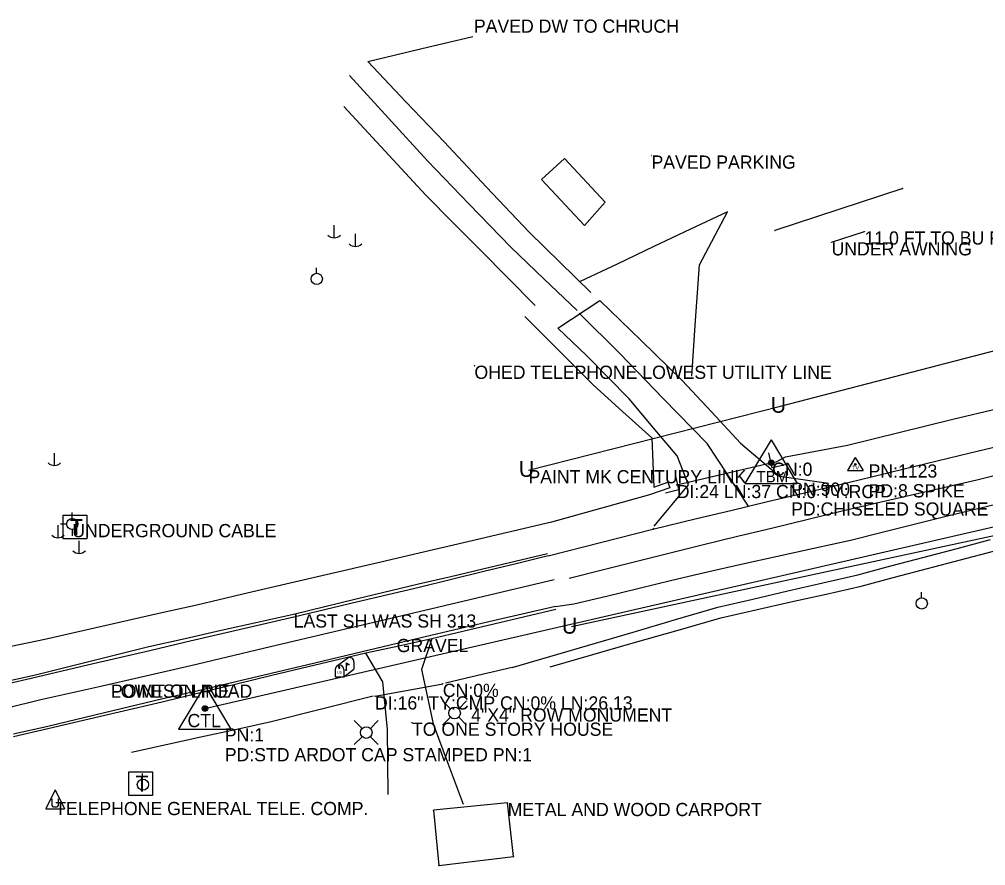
# Model space of a CAD drawing. Extents: x 1568433 to 1572450, y 731863 to 733450.
# Drawn here: x 1569044.4 to 1569410.1, y 731914 to 732234.5 of the extents above; entities that cross this region are included whole.
import ezdxf

# ---------------------------------------------------------------- set-up
doc = ezdxf.new("R2010")
doc.units = 0
for name, color, linetype in [('Default', 7, 'Continuous'), ('S_BASELINE', 7, 'Continuous'), ('S_BUILDING', 7, 'Continuous'), ('S_BUILDING_ANNOT', 7, 'Continuous'), ('S_CROSS_DRAIN', 7, 'Continuous'), ('S_CROSS_DRAIN_ANNOT', 7, 'Continuous'), ('S_DITCHLINE', 7, 'Continuous'), ('S_DRG_PT_SYM', 7, 'Continuous'), ('S_DRIVEWAY', 7, 'Continuous'), ('S_DRIVEWAY_ANNOT', 7, 'Continuous'), ('S_EDGE_BITUMINOUS', 7, 'Continuous'), ('S_EDGE_PAVEMENT', 7, 'Continuous'), ('S_EDGE_PAVEMENT_ANNOT', 7, 'Continuous'), ('S_ELECTRIC_UTILITIES_ANNOT', 7, 'Continuous'), ('S_HEADWALL', 7, 'Continuous'), ('S_MAILBOX', 7, 'Continuous'), ('S_MISC_STRUCTURES_ANNOT', 7, 'Continuous'), ('S_MSC_PT_SYM', 7, 'Continuous'), ('S_PAVEMENT_CROWN', 7, 'Continuous'), ('S_PRIMARY_CTL', 7, 'Continuous'), ('S_PRIMARY_CTL_ANNOT', 7, 'Continuous'), ('S_SECONDARY_CTL', 7, 'Continuous'), ('S_SECONDARY_CTL_ANNOT', 7, 'Continuous'), ('S_SHOULDER', 7, 'Continuous'), ('S_SHOULDER_ANNOT', 7, 'Continuous'), ('S_SIDE_DRAIN', 7, 'Continuous'), ('S_SIDE_DRAIN_ANNOT', 7, 'Continuous'), ('S_STR_PT_SYM', 7, 'Continuous'), ('S_SURVEY_TEXT_ANNOT', 7, 'Continuous'), ('S_TELEPHONE_UTILITIES', 7, 'Continuous'), ('S_UNDERGROUND_CABLE', 7, 'Continuous'), ('S_UNDERGROUND_CABLE_ANNOT', 7, 'Continuous'), ('S_UTILITY_POLE', 7, 'Continuous'), ('S_UTILITY_POLE_ANNOT', 7, 'Continuous'), ('S_UTL_PT_SYM', 7, 'Continuous')]:
    doc.layers.add(name, color=color, linetype=linetype)

msp = doc.modelspace()

# ---------------------------------------------------------------- linework, layer by layer
at = {"layer": 'S_BASELINE'}
msp.add_line((1569114.63, 731973.54), (1569838.9, 732140.65), dxfattribs=at)
at = {"layer": 'S_BUILDING'}
for p, q in [((1569378.7, 732170.43), (1569330.35, 732154.58)), ((1569351.75, 732150.1), (1569364.23, 732154.2)), ((1569229.18, 731937.78), (1569201.12, 731935.01)), ((1569201.12, 731935.01), (1569203.16, 731914.06)), ((1569231.45, 731917.5), (1569229.18, 731937.78)), ((1569203.16, 731914.06), (1569231.45, 731917.5))]:
    msp.add_line(p, q, dxfattribs=at)
at = {"layer": 'S_CROSS_DRAIN'}
msp.add_line((1569293.19, 732058.18), (1569329.29, 732066.65), dxfattribs=at)
at = {"layer": 'S_DITCHLINE'}
for points in [[(1569235.71, 732121.94), (1569248.7, 732108.98), (1569261.69, 732096.03), (1569272.71, 732086.03), (1569283.73, 732076.03), (1569284.45, 732057.39), (1569289.75, 732059.27), (1569290.58, 732057.14), (1569282.85, 732054.43), (1569282.85, 732054.43), (1569245.78, 732044.09)], [(1569330.52, 732066.86), (1569334.31, 732068.88), (1569357.83, 732073.3), (1569377.75, 732078.21), (1569397.67, 732083.12), (1569414.63, 732087.18), (1569431.6, 732091.25), (1569444.47, 732094.14), (1569457.35, 732097.03)], [(1569245.78, 732044.09), (1569229.1, 732040.19), (1569212.42, 732036.29), (1569195.74, 732032.39), (1569179.05, 732028.49), (1569162.17, 732024.54), (1569145.29, 732020.6), (1569128.41, 732016.66), (1569111.52, 732012.72), (1569097.17, 732009.46), (1569082.81, 732006.2), (1569068.45, 732002.95), (1569054.1, 731999.69), (1569041.3, 731996.99)], [(1569230.86, 731989.03), (1569276.66, 732002.49), (1569292.69, 732007.2), (1569308.72, 732011.9), (1569321.96, 732014.97), (1569335.2, 732018.04), (1569348.44, 732021.11), (1569361.68, 732024.18), (1569374.24, 732027.5), (1569386.79, 732030.82), (1569399.35, 732034.15), (1569411.9, 732037.47)], [(1569245.25, 731989.34), (1569261.39, 731993.97), (1569277.52, 731998.6), (1569293.66, 732003.24), (1569309.8, 732007.87), (1569323.1, 732010.87), (1569336.41, 732013.87), (1569349.71, 732016.87), (1569363.02, 732019.87), (1569375.53, 732023.2), (1569388.04, 732026.52), (1569400.55, 732029.85), (1569413.06, 732033.17)], [(1569230.86, 731989.03), (1569217.88, 731986.01), (1569205.69, 731983.18)], [(1569178.31, 731978.15), (1569158.76, 731973.27), (1569139.22, 731968.39), (1569126.12, 731965.51), (1569113.02, 731962.64), (1569099.92, 731959.77), (1569086.82, 731956.89)]]:
    msp.add_lwpolyline(points, dxfattribs=at)
at = {"layer": 'S_DRG_PT_SYM'}
for points in [[(1569329.29, 732066.65), (1569329.29, 732066.7), (1569329.29, 732066.65), (1569329.24, 732066.65), (1569329.29, 732066.65), (1569329.29, 732066.6), (1569329.29, 732066.65), (1569329.34, 732066.65)], [(1569293.19, 732058.18), (1569293.19, 732058.23), (1569293.19, 732058.18), (1569293.14, 732058.18), (1569293.19, 732058.18), (1569293.19, 732058.13), (1569293.19, 732058.18), (1569293.24, 732058.18)], [(1569204.64, 731982.9), (1569204.64, 731982.95), (1569204.64, 731982.9), (1569204.59, 731982.9), (1569204.64, 731982.9), (1569204.64, 731982.85), (1569204.64, 731982.9), (1569204.69, 731982.9)], [(1569178.99, 731978.14), (1569178.99, 731978.19), (1569178.99, 731978.14), (1569178.94, 731978.14), (1569178.99, 731978.14), (1569178.99, 731978.09), (1569178.99, 731978.14), (1569179.04, 731978.14)]]:
    msp.add_lwpolyline(points, dxfattribs=at)
at = {"layer": 'S_DRIVEWAY'}
for points in [[(1569200.48, 731999.88), (1569196.61, 731988.29), (1569200.94, 731967.71), (1569206.65, 731952.48), (1569212.37, 731937.25)], [(1569183.93, 731940.91), (1569183.72, 731965.59), (1569181.96, 731983.57), (1569175.58, 731994.49)]]:
    msp.add_lwpolyline(points, dxfattribs=at)
at = {"layer": 'S_EDGE_BITUMINOUS'}
for points in [[(1569298.89, 732099.43), (1569300.32, 732120.47), (1569301.76, 732141.5), (1569312.34, 732161.57), (1569298.43, 732154.99), (1569284.52, 732148.42), (1569270.61, 732141.85), (1569256.69, 732135.28)], [(1569284.58, 732042.58), (1569297.66, 732058.22), (1569293.33, 732069.23), (1569284.24, 732080), (1569275.15, 732090.77), (1569259.07, 732107.25), (1569248.17, 732117.52), (1569264.11, 732127.99), (1569279.71, 732112.87), (1569295.2, 732097.76), (1569306.27, 732085.85), (1569317.34, 732073.95), (1569332.08, 732061.51), (1569350.62, 732058.91)]]:
    msp.add_lwpolyline(points, dxfattribs=at)
at = {"layer": 'S_EDGE_PAVEMENT'}
for points in [[(1569176.31, 732218.53), (1569196.17, 732223.28), (1569216.02, 732228.03)], [(1569260.66, 732131.1), (1569248.99, 732142.5), (1569237.31, 732153.9), (1569221.22, 732170.99), (1569205.13, 732188.08), (1569190.72, 732203.3), (1569176.31, 732218.53)], [(1569167.24, 732201.47), (1569182.71, 732184.7), (1569198.17, 732167.93), (1569208.51, 732157.48), (1569218.86, 732147.03), (1569229.2, 732136.58), (1569239.54, 732126.13)], [(1569284.5, 732041.74), (1569284.16, 732041.41), (1569300.65, 732045.51), (1569314.09, 732048.68), (1569327.53, 732051.86), (1569340.97, 732055.03), (1569354.41, 732058.2), (1569354.36, 732058.19), (1569366.83, 732061.23), (1569379.29, 732064.28), (1569391.76, 732067.33), (1569404.23, 732070.38), (1569417.48, 732073.55)], [(1569254.28, 732013.13), (1569266.64, 732016.12), (1569279, 732019.1), (1569291.36, 732022.09), (1569303.72, 732025.08), (1569317.51, 732028.13), (1569331.29, 732031.19), (1569345.08, 732034.24), (1569358.87, 732037.3), (1569371.47, 732040.43), (1569384.08, 732043.56), (1569396.68, 732046.69), (1569409.29, 732049.82), (1569422.64, 732052.99)], [(1569244.55, 732031.33), (1569284.16, 732041.41)], [(1569244.55, 732031.33), (1569232.35, 732028.34), (1569220.15, 732025.35), (1569207.95, 732022.36), (1569195.75, 732019.37), (1569172.01, 732013.76), (1569148.27, 732008.16), (1569134.64, 732004.97), (1569121.01, 732001.79), (1569107.37, 731998.6), (1569093.74, 731995.42), (1569072.35, 731990.39), (1569050.96, 731985.36), (1569038.07, 731982.36)], [(1569247.28, 732012.21), (1569223.69, 732006.71), (1569200.1, 732001.2), (1569176.81, 731995.63), (1569153.51, 731990.05), (1569139.68, 731986.8), (1569125.85, 731983.54), (1569112.02, 731980.28), (1569098.2, 731977.03), (1569076.66, 731971.9), (1569055.13, 731966.76), (1569042.19, 731963.8)], [(1569247.28, 732012.21), (1569254.28, 732013.13)]]:
    msp.add_lwpolyline(points, dxfattribs=at)
msp.add_lwpolyline([(1569258.24, 732156.37), (1569241.99, 732173.86), (1569250.76, 732181.76), (1569266.14, 732165.25)], close=True, dxfattribs=at)
at = {"layer": 'S_HEADWALL'}
for points in [[(1569334.25, 732065.85), (1569329.28, 732064.69), (1569327.97, 732070.34)], [(1569288.91, 732055.2), (1569293.98, 732056.45), (1569292.76, 732062.09)]]:
    msp.add_lwpolyline(points, dxfattribs=at)
at = {"layer": 'S_MAILBOX'}
for p, q in [((1569164.46, 731989.52), (1569168.6, 731992.63)), ((1569168.08, 731990.81), (1569168.08, 731988.09)), ((1569171.03, 731991.15), (1569171.03, 731988.44)), ((1569163.91, 731988.24), (1569163.91, 731985.53)), ((1569163.91, 731985.53), (1569167.23, 731985.53)), ((1569167.23, 731985.53), (1569171.03, 731988.44)), ((1569167.23, 731988.24), (1569167.23, 731985.53))]:
    msp.add_line(p, q, dxfattribs=at)
for points in [[(1569165.09, 731989.36), (1569165.31, 731989.22), (1569165.31, 731988.83), (1569165.62, 731988.83), (1569165.62, 731989.19), (1569165.43, 731989.44), (1569165.09, 731989.39)], [(1569168.08, 731990.81), (1569169.19, 731990.14), (1569168.08, 731989.79)]]:
    msp.add_lwpolyline(points, dxfattribs=at)
for centre, end in [((1569165.57, 731988.24), 180), ((1569169.37, 731991.15), 117.5718)]:
    msp.add_arc(centre, 1.66, 0, end, dxfattribs=at)
msp.add_ellipse((1569168.08, 731988.09), major_axis=(0.145, 0.132), ratio=0.564646, dxfattribs=at)
at = {"layer": 'S_MSC_PT_SYM'}
for points in [[(1569216.4, 732234.43), (1569216.4, 732234.48), (1569216.4, 732234.43), (1569216.35, 732234.43), (1569216.4, 732234.43), (1569216.4, 732234.38), (1569216.4, 732234.43), (1569216.45, 732234.43)], [(1569283.61, 732182.94), (1569283.61, 732182.99), (1569283.61, 732182.94), (1569283.56, 732182.94), (1569283.61, 732182.94), (1569283.61, 732182.89), (1569283.61, 732182.94), (1569283.66, 732182.94)], [(1569079.06, 731982.61), (1569079.06, 731982.66), (1569079.06, 731982.61), (1569079.01, 731982.61), (1569079.06, 731982.61), (1569079.06, 731982.56), (1569079.06, 731982.61), (1569079.11, 731982.61)], [(1569215.39, 731973.56), (1569215.39, 731973.61), (1569215.39, 731973.56), (1569215.34, 731973.56), (1569215.39, 731973.56), (1569215.39, 731973.51), (1569215.39, 731973.56), (1569215.44, 731973.56)], [(1569192.98, 731968.19), (1569192.98, 731968.24), (1569192.98, 731968.19), (1569192.93, 731968.19), (1569192.98, 731968.19), (1569192.98, 731968.14), (1569192.98, 731968.19), (1569193.03, 731968.19)]]:
    msp.add_lwpolyline(points, dxfattribs=at)
at = {"layer": 'S_PAVEMENT_CROWN'}
for points in [[(1569255.44, 732124.25), (1569242.92, 732136.22), (1569230.41, 732148.19), (1569214.66, 732164.54), (1569198.92, 732180.9), (1569184.12, 732197.03), (1569169.33, 732213.17)], [(1569320.37, 732050.12), (1569312.56, 732062.02), (1569304.75, 732073.91), (1569288.06, 732090.98), (1569271.62, 732108.02), (1569256.27, 732123.18)], [(1569252.43, 732022.86), (1569265.01, 732026.02), (1569277.6, 732029.17), (1569290.18, 732032.33), (1569302.76, 732035.49), (1569316.14, 732038.73), (1569329.52, 732041.98), (1569342.9, 732045.23), (1569356.28, 732048.47), (1569368.88, 732051.37), (1569381.49, 732054.27), (1569394.09, 732057.17), (1569406.7, 732060.07), (1569420.02, 732063.45)], [(1569246.77, 732022.29), (1569234.54, 732019.39), (1569222.31, 732016.49), (1569210.08, 732013.59), (1569197.85, 732010.69), (1569174.23, 732005.1), (1569150.61, 731999.52), (1569136.85, 731996.26), (1569123.1, 731993), (1569109.35, 731989.74), (1569095.6, 731986.48), (1569074.08, 731981.67), (1569052.57, 731976.85), (1569039.82, 731973.68)]]:
    msp.add_lwpolyline(points, dxfattribs=at)
at = {"layer": 'S_PRIMARY_CTL'}
for p, q in [((1569328.96, 732075.28), (1569318.93, 732058.77)), ((1569328.96, 732075.28), (1569318.93, 732058.77)), ((1569328.96, 732075.28), (1569338.78, 732058.77)), ((1569328.96, 732075.28), (1569338.78, 732058.77)), ((1569318.93, 732058.77), (1569338.78, 732058.77)), ((1569318.93, 732058.77), (1569338.78, 732058.77)), ((1569114.63, 731982.24), (1569104.6, 731965.73)), ((1569114.63, 731982.24), (1569104.6, 731965.73)), ((1569114.63, 731982.24), (1569124.45, 731965.73)), ((1569114.63, 731982.24), (1569124.45, 731965.73)), ((1569104.6, 731965.73), (1569124.45, 731965.73)), ((1569104.6, 731965.73), (1569124.45, 731965.73))]:
    msp.add_line(p, q, dxfattribs=at)
for centre, radius in [((1569328.96, 732066.58), 1.04), ((1569328.96, 732066.58), 1.04), ((1569328.96, 732066.58), 0.609), ((1569328.96, 732066.58), 0.609), ((1569328.96, 732066.58), 0.344), ((1569328.96, 732066.58), 0.344), ((1569114.63, 731973.54), 1.04), ((1569114.63, 731973.54), 1.04), ((1569114.63, 731973.54), 0.609), ((1569114.63, 731973.54), 0.609), ((1569114.63, 731973.54), 0.344), ((1569114.63, 731973.54), 0.344)]:
    msp.add_circle(centre, radius, dxfattribs=at)
at = {"layer": 'S_SECONDARY_CTL'}
for p, q in [((1569360.76, 732068.58), (1569357.75, 732063.63)), ((1569360.76, 732068.58), (1569363.71, 732063.63)), ((1569357.75, 732063.63), (1569363.71, 732063.63))]:
    msp.add_line(p, q, dxfattribs=at)
for radius in [0.311, 0.183, 0.103]:
    msp.add_circle((1569360.76, 732065.97), radius, dxfattribs=at)
at = {"layer": 'S_SHOULDER'}
for points in [[(1569244.23, 732032.04), (1569232.03, 732029.18), (1569219.83, 732026.31), (1569207.63, 732023.44), (1569195.43, 732020.57), (1569171.82, 732014.87), (1569148.2, 732009.17), (1569134.51, 732006.09), (1569120.82, 732003.02), (1569107.12, 731999.95), (1569093.43, 731996.88), (1569072.24, 731991.58), (1569051.04, 731986.28), (1569038.05, 731983.33)], [(1569247.42, 732010.97), (1569223.95, 732005.43), (1569200.48, 731999.88), (1569188.03, 731997.19), (1569175.58, 731994.49), (1569153.73, 731989.37), (1569139.91, 731986.01), (1569126.09, 731982.65), (1569112.27, 731979.29), (1569098.45, 731975.93), (1569076.79, 731970.89), (1569055.13, 731965.85), (1569042.2, 731962.81)]]:
    msp.add_lwpolyline(points, dxfattribs=at)
at = {"layer": 'S_SIDE_DRAIN'}
msp.add_line((1569178.99, 731978.14), (1569204.64, 731982.9), dxfattribs=at)
at = {"layer": 'S_STR_PT_SYM'}
for points in [[(1569378.7, 732170.43), (1569378.7, 732170.48), (1569378.7, 732170.43), (1569378.65, 732170.43), (1569378.7, 732170.43), (1569378.7, 732170.38), (1569378.7, 732170.43), (1569378.75, 732170.43)], [(1569330.35, 732154.58), (1569330.35, 732154.63), (1569330.35, 732154.58), (1569330.3, 732154.58), (1569330.35, 732154.58), (1569330.35, 732154.53), (1569330.35, 732154.58), (1569330.4, 732154.58)], [(1569364.23, 732154.2), (1569364.23, 732154.25), (1569364.23, 732154.2), (1569364.18, 732154.2), (1569364.23, 732154.2), (1569364.23, 732154.15), (1569364.23, 732154.2), (1569364.28, 732154.2)], [(1569351.75, 732150.1), (1569351.75, 732150.15), (1569351.75, 732150.1), (1569351.7, 732150.1), (1569351.75, 732150.1), (1569351.75, 732150.05), (1569351.75, 732150.1), (1569351.8, 732150.1)], [(1569201.12, 731935.01), (1569201.12, 731935.06), (1569201.12, 731935.01), (1569201.07, 731935.01), (1569201.12, 731935.01), (1569201.12, 731934.96), (1569201.12, 731935.01), (1569201.17, 731935.01)], [(1569229.18, 731937.78), (1569229.18, 731937.83), (1569229.18, 731937.78), (1569229.13, 731937.78), (1569229.18, 731937.78), (1569229.18, 731937.73), (1569229.18, 731937.78), (1569229.23, 731937.78)], [(1569231.45, 731917.5), (1569231.45, 731917.55), (1569231.45, 731917.5), (1569231.4, 731917.5), (1569231.45, 731917.5), (1569231.45, 731917.45), (1569231.45, 731917.5), (1569231.5, 731917.5)], [(1569203.16, 731914.06), (1569203.16, 731914.11), (1569203.16, 731914.06), (1569203.11, 731914.06), (1569203.16, 731914.06), (1569203.16, 731914.01), (1569203.16, 731914.06), (1569203.21, 731914.06)]]:
    msp.add_lwpolyline(points, dxfattribs=at)
at = {"layer": 'S_TELEPHONE_UTILITIES'}
for points in [[(1569060.93, 732037.74), (1569060.93, 732046.74), (1569069.93, 732046.74), (1569069.93, 732037.74)], [(1569085.79, 731940.58), (1569085.79, 731949.58), (1569094.79, 731949.58), (1569094.79, 731940.58)]]:
    msp.add_lwpolyline(points, close=True, dxfattribs=at)
at = {"layer": 'S_UNDERGROUND_CABLE'}
for p, q in [((1569332.4, 732088.07), (1569468.44, 732123.27)), ((1569237.05, 732063.8), (1569332.4, 732088.07)), ((1569552.71, 732069.09), (1569253.35, 732004.42)), ((1569057.97, 731942.69), (1569054.44, 731935.59)), ((1569057.97, 731942.69), (1569061.45, 731935.59)), ((1569056.76, 731936.83), (1569056.76, 731939.28)), ((1569059.13, 731939.28), (1569059.13, 731936.83)), ((1569054.44, 731935.59), (1569061.45, 731935.59)), ((1569057.38, 731936.18), (1569056.76, 731936.83)), ((1569058.59, 731936.18), (1569057.38, 731936.18)), ((1569059.13, 731936.83), (1569058.59, 731936.18))]:
    msp.add_line(p, q, dxfattribs=at)
at = {"layer": 'S_UTILITY_POLE'}
for p, q in [((1569163.47, 732156.5), (1569163.47, 732151.77)), ((1569171.54, 732153.22), (1569171.54, 732148.49)), ((1569156.81, 732138.35), (1569156.81, 732140.46)), ((1569057.62, 732070.28), (1569057.62, 732065.56)), ((1569064.41, 732045.5), (1569064.41, 732047.75)), ((1569058.93, 732042.92), (1569058.93, 732038.19)), ((1569062.32, 732043.37), (1569059.99, 732043.37)), ((1569064.49, 732038.95), (1569064.49, 732041.28)), ((1569066.96, 732037), (1569066.96, 732032.27)), ((1569385.78, 732015.44), (1569385.78, 732017.54)), ((1569207.51, 731973.39), (1569204.53, 731976.38)), ((1569210.69, 731973.39), (1569213.67, 731976.38)), ((1569174.09, 731966.01), (1569171.1, 731968.99)), ((1569177.27, 731966.01), (1569180.25, 731968.99)), ((1569207.51, 731970.22), (1569204.53, 731967.23)), ((1569210.69, 731970.22), (1569213.67, 731967.23)), ((1569174.09, 731962.83), (1569171.1, 731959.85)), ((1569177.27, 731962.83), (1569180.25, 731959.85)), ((1569091.03, 731946.83), (1569091.03, 731948.94))]:
    msp.add_line(p, q, dxfattribs=at)
for centre, radius in [((1569156.94, 732136.21), 2.13), ((1569064.41, 732043.39), 2.13), ((1569385.91, 732013.3), 2.13), ((1569209.11, 731971.81), 2.21), ((1569175.69, 731964.43), 2.21), ((1569091.15, 731944.69), 2.13)]:
    msp.add_circle(centre, radius, dxfattribs=at)
for centre in [(1569163.54, 732155.2), (1569171.6, 732151.92), (1569057.68, 732068.98), (1569058.99, 732041.62), (1569067.02, 732035.69)]:
    msp.add_arc(centre, 3.41, 226.3972, 313.6028, dxfattribs=at)
at = {"layer": 'S_UTL_PT_SYM'}
for points in [[(1569216.62, 732103.35), (1569216.62, 732103.4), (1569216.62, 732103.35), (1569216.57, 732103.35), (1569216.62, 732103.35), (1569216.62, 732103.3), (1569216.62, 732103.35), (1569216.67, 732103.35)], [(1569079.06, 731982.61), (1569079.06, 731982.66), (1569079.06, 731982.61), (1569079.01, 731982.61), (1569079.06, 731982.61), (1569079.06, 731982.56), (1569079.06, 731982.61), (1569079.11, 731982.61)]]:
    msp.add_lwpolyline(points, dxfattribs=at)

# ---------------------------------------------------------------- texts
at = {"layer": 'Default'}
for p in [(1569328.77, 732085.52), (1569233.42, 732061.25), (1569249.72, 732001.87)]:
    msp.add_text('U', height=6, dxfattribs=at).set_placement(p)
at = {"layer": 'S_BUILDING_ANNOT'}
for s, p in [('11.0 FT TO BU FACE', (1569364.23, 732149.2)), ('UNDER AWNING', (1569351.75, 732145.1)), ('METAL AND WOOD CARPORT', (1569229.18, 731932.78))]:
    msp.add_text(s, height=5, dxfattribs=at).set_placement(p)
at = {"layer": 'S_CROSS_DRAIN_ANNOT'}
for s, p in [('CN:0', (1569329.29, 732061.65)), ('DI:24 LN:37 CN:0 TY:RCP', (1569293.19, 732053.18))]:
    msp.add_text(s, height=5, dxfattribs=at).set_placement(p)
at = {"layer": 'S_DRIVEWAY_ANNOT'}
msp.add_text('GRAVEL', height=5, dxfattribs=at).set_placement((1569187.21, 731994.88))
at = {"layer": 'S_EDGE_PAVEMENT_ANNOT'}
msp.add_text('LAST SH WAS SH 313', height=5, dxfattribs=at).set_placement((1569148.2, 732004.17))
at = {"layer": 'S_ELECTRIC_UTILITIES_ANNOT'}
for s, p in [('OHED TELEPHONE LOWEST UTILITY LINE', (1569216.62, 732098.35)), ('LOWEST LINE', (1569079.06, 731977.61))]:
    msp.add_text(s, height=5, dxfattribs=at).set_placement(p)
at = {"layer": 'S_MAILBOX'}
msp.add_text('US', height=0.96, rotation=360, dxfattribs=at).set_placement((1569164.67, 731986.72))
at = {"layer": 'S_MISC_STRUCTURES_ANNOT'}
msp.add_text('4"X4" ROW MONUMENT', height=5, dxfattribs=at).set_placement((1569215.39, 731968.56))
at = {"layer": 'S_PRIMARY_CTL'}
for s, height, p in [('TBM', 4.287, (1569323.31, 732059.19)), ('CTL', 5, (1569108.04, 731966.46))]:
    msp.add_text(s, height=height, rotation=360, dxfattribs=at).set_placement(p)
for s, height, p in [('TBM', 4.287, (1569323.31, 732059.19)), ('CTL', 5, (1569108.04, 731966.46))]:
    msp.add_text(s, height=height, dxfattribs=at).set_placement(p)
at = {"layer": 'S_PRIMARY_CTL_ANNOT'}
for s, p in [('PN:900', (1569336.46, 732054.08)), ('PD:CHISELED SQUARE IN HW', (1569336.46, 732046.58)), ('PN:1', (1569122.13, 731961.04)), ('PD:STD ARDOT CAP STAMPED PN:1', (1569122.13, 731953.54))]:
    msp.add_text(s, height=5, dxfattribs=at).set_placement(p)
at = {"layer": 'S_SECONDARY_CTL'}
msp.add_text('TV', height=1.5, rotation=360, dxfattribs=at).set_placement((1569359.56, 732063.96))
at = {"layer": 'S_SECONDARY_CTL_ANNOT'}
for s, p in [('PN:1123', (1569365.76, 732060.97)), ('PD:8 SPIKE', (1569365.76, 732053.47))]:
    msp.add_text(s, height=5, dxfattribs=at).set_placement(p)
at = {"layer": 'S_SHOULDER_ANNOT'}
msp.add_text('LAST SH WAS SH 313', height=5, dxfattribs=at).set_placement((1569148.2, 732004.17))
at = {"layer": 'S_SIDE_DRAIN_ANNOT'}
for s, p in [('CN:0%', (1569204.64, 731977.9)), ('DI:16" TY:CMP CN:0% LN:26.13', (1569178.99, 731973.14))]:
    msp.add_text(s, height=5, dxfattribs=at).set_placement(p)
at = {"layer": 'S_SURVEY_TEXT_ANNOT'}
for s, p in [('PAVED DW TO CHRUCH', (1569216.4, 732229.43)), ('PAVED PARKING', (1569283.61, 732177.94)), ('POINT ON ROAD', (1569079.06, 731977.61)), ('TO ONE STORY HOUSE', (1569192.98, 731963.19))]:
    msp.add_text(s, height=5, dxfattribs=at).set_placement(p)
at = {"layer": 'S_TELEPHONE_UTILITIES'}
for p in [(1569063.49, 732039.24), (1569088.35, 731942.08)]:
    msp.add_text('T', height=6, rotation=360, dxfattribs=at).set_placement(p)
at = {"layer": 'S_UNDERGROUND_CABLE_ANNOT'}
msp.add_text('PAINT MK CENTURY LINK', height=5, dxfattribs=at).set_placement((1569237.05, 732058.8))
at = {"layer": 'S_UTILITY_POLE_ANNOT'}
for s, p in [('UNDERGROUND CABLE', (1569064.41, 732038.39)), ('TELEPHONE GENERAL TELE. COMP.', (1569057.97, 731933.15))]:
    msp.add_text(s, height=5, dxfattribs=at).set_placement(p)

doc.saveas('drawing.dxf')
